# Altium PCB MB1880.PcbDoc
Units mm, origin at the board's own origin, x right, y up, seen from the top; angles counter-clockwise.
Board outline 30 x 30 mm, 2 copper layers (Top Layer, Bottom Layer), stack 1.499 mm thick; 19 components, 23 nets, 96 pads, 171 vias.
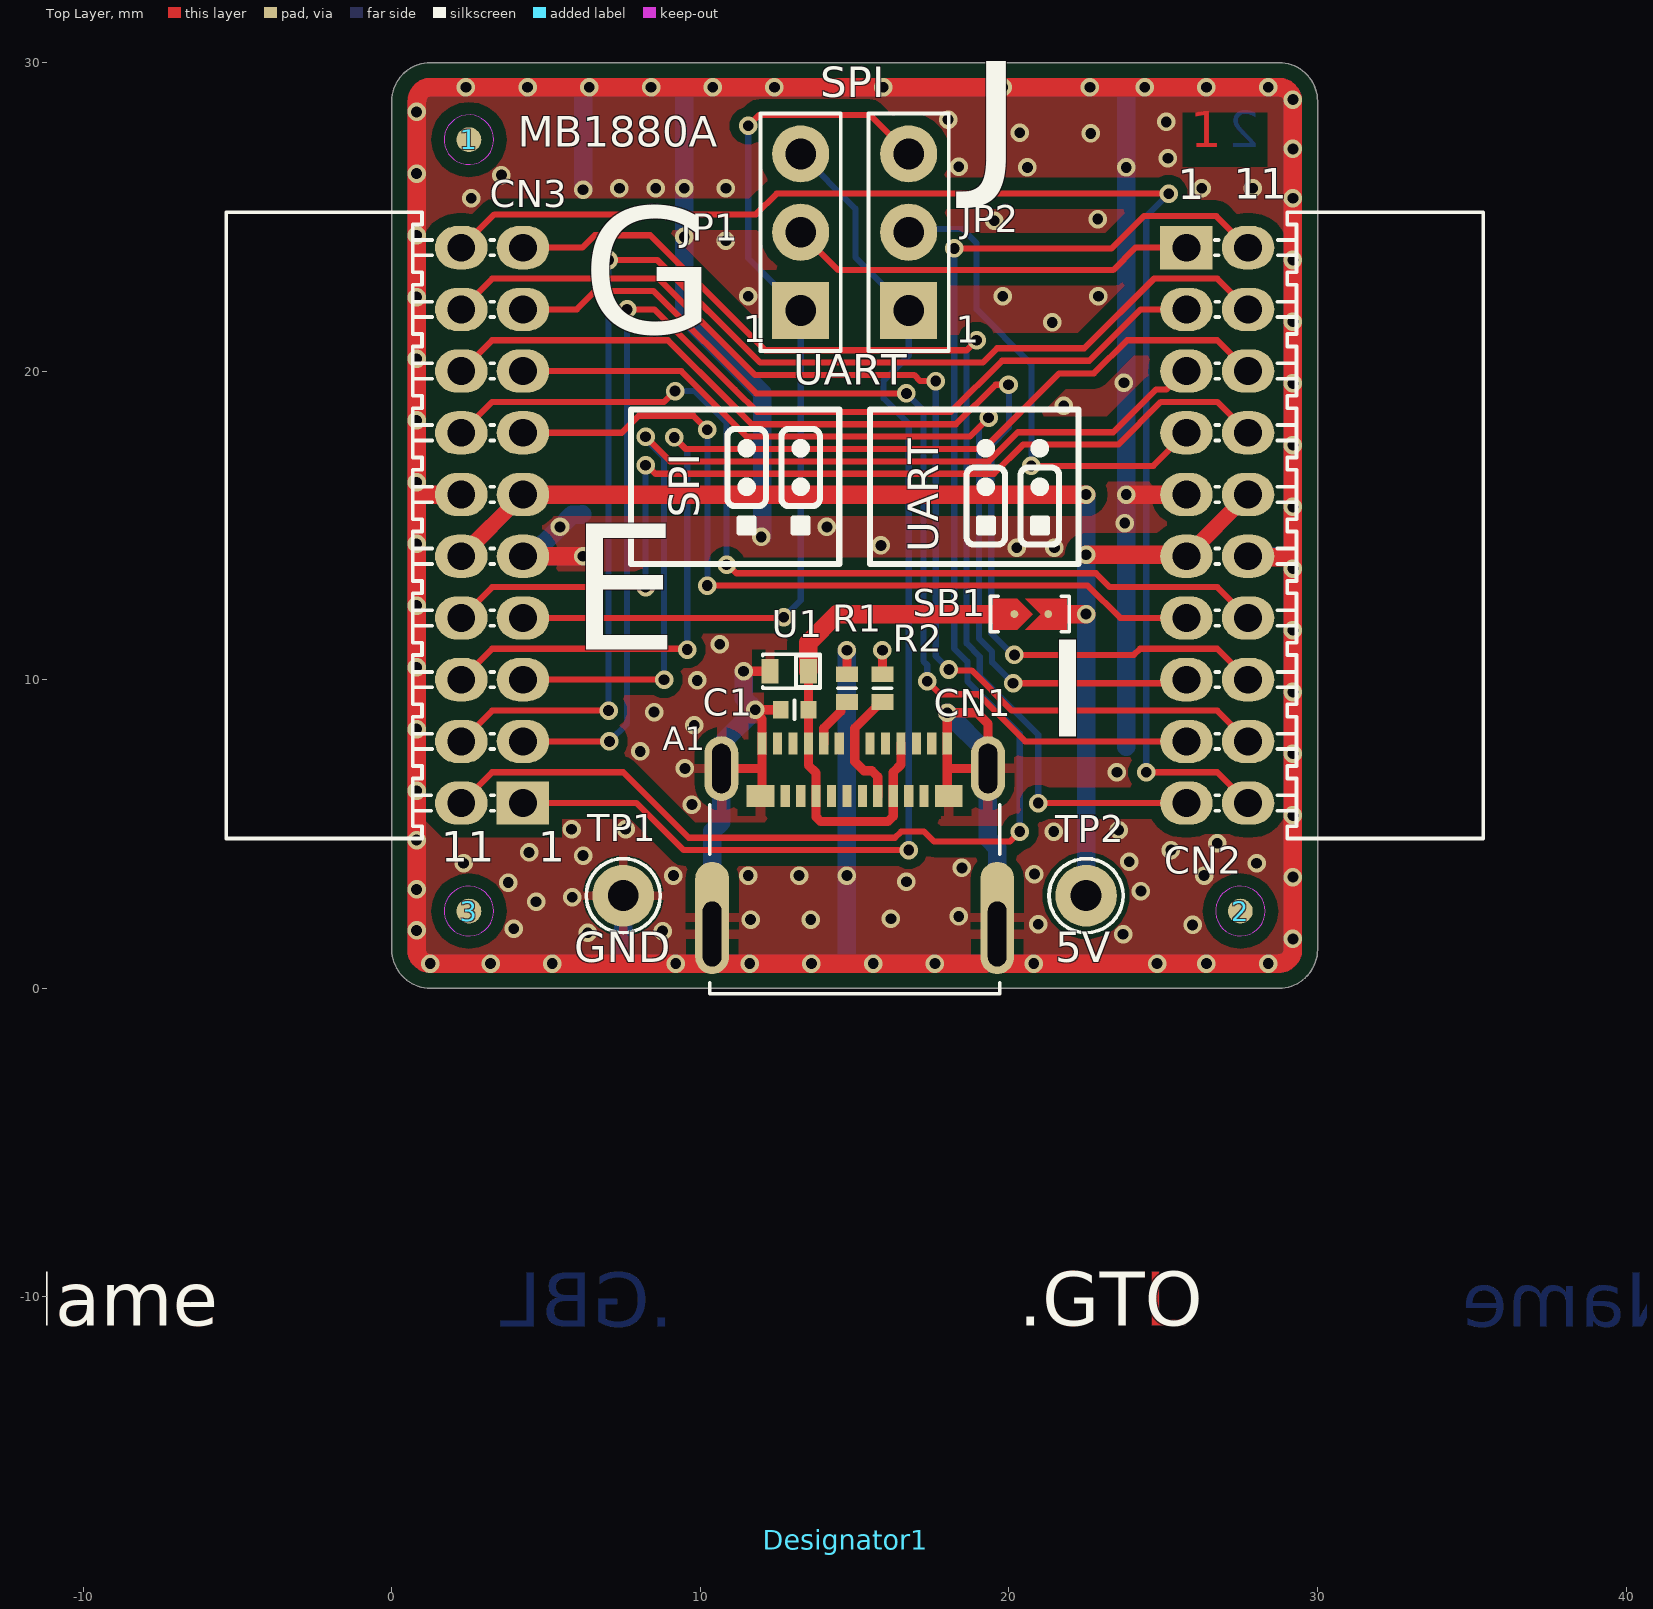
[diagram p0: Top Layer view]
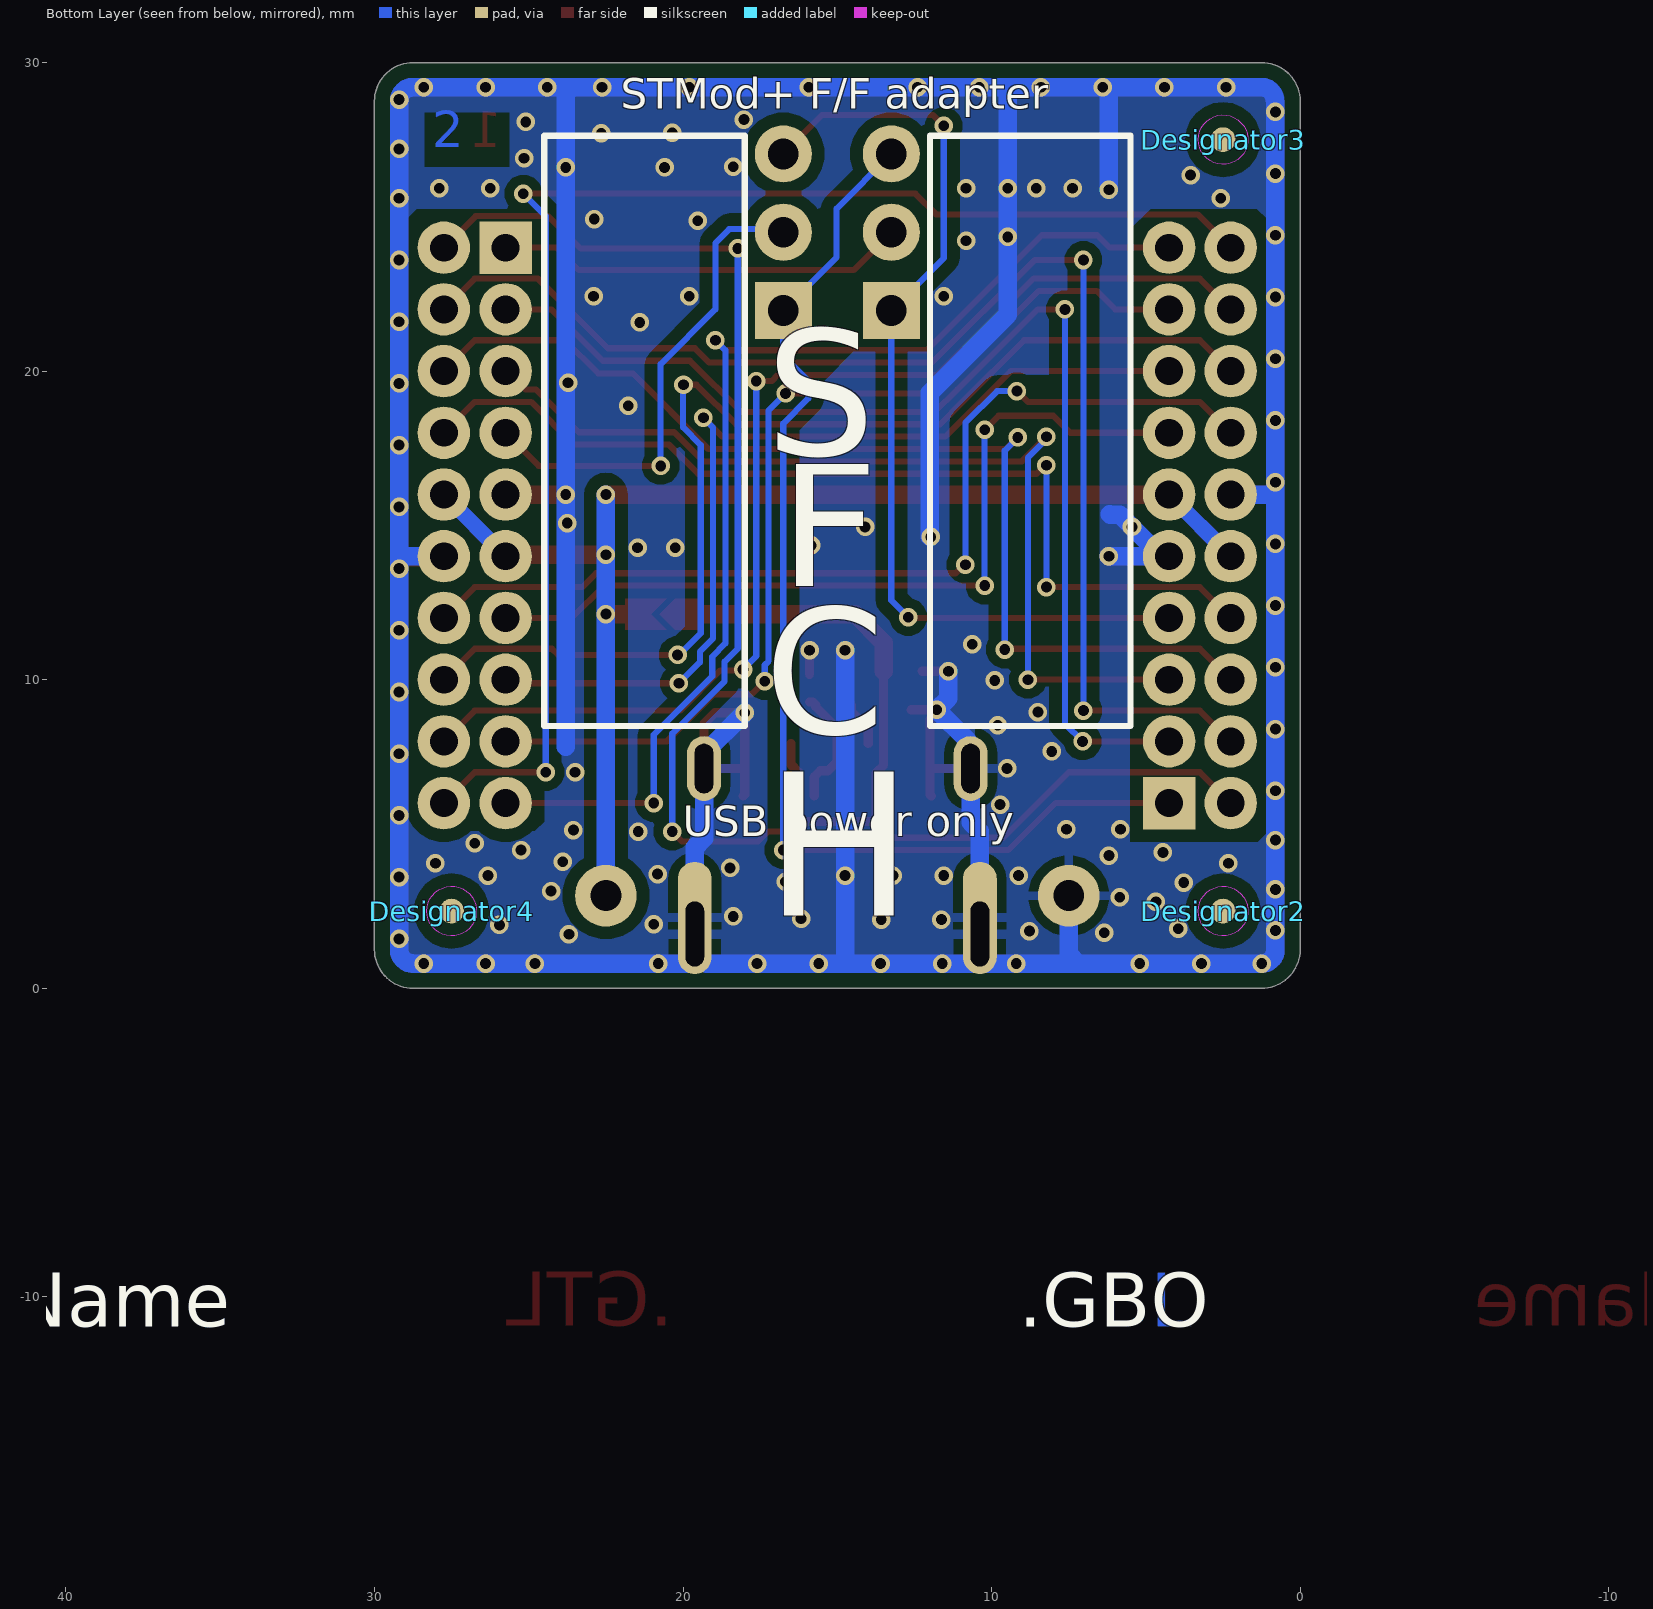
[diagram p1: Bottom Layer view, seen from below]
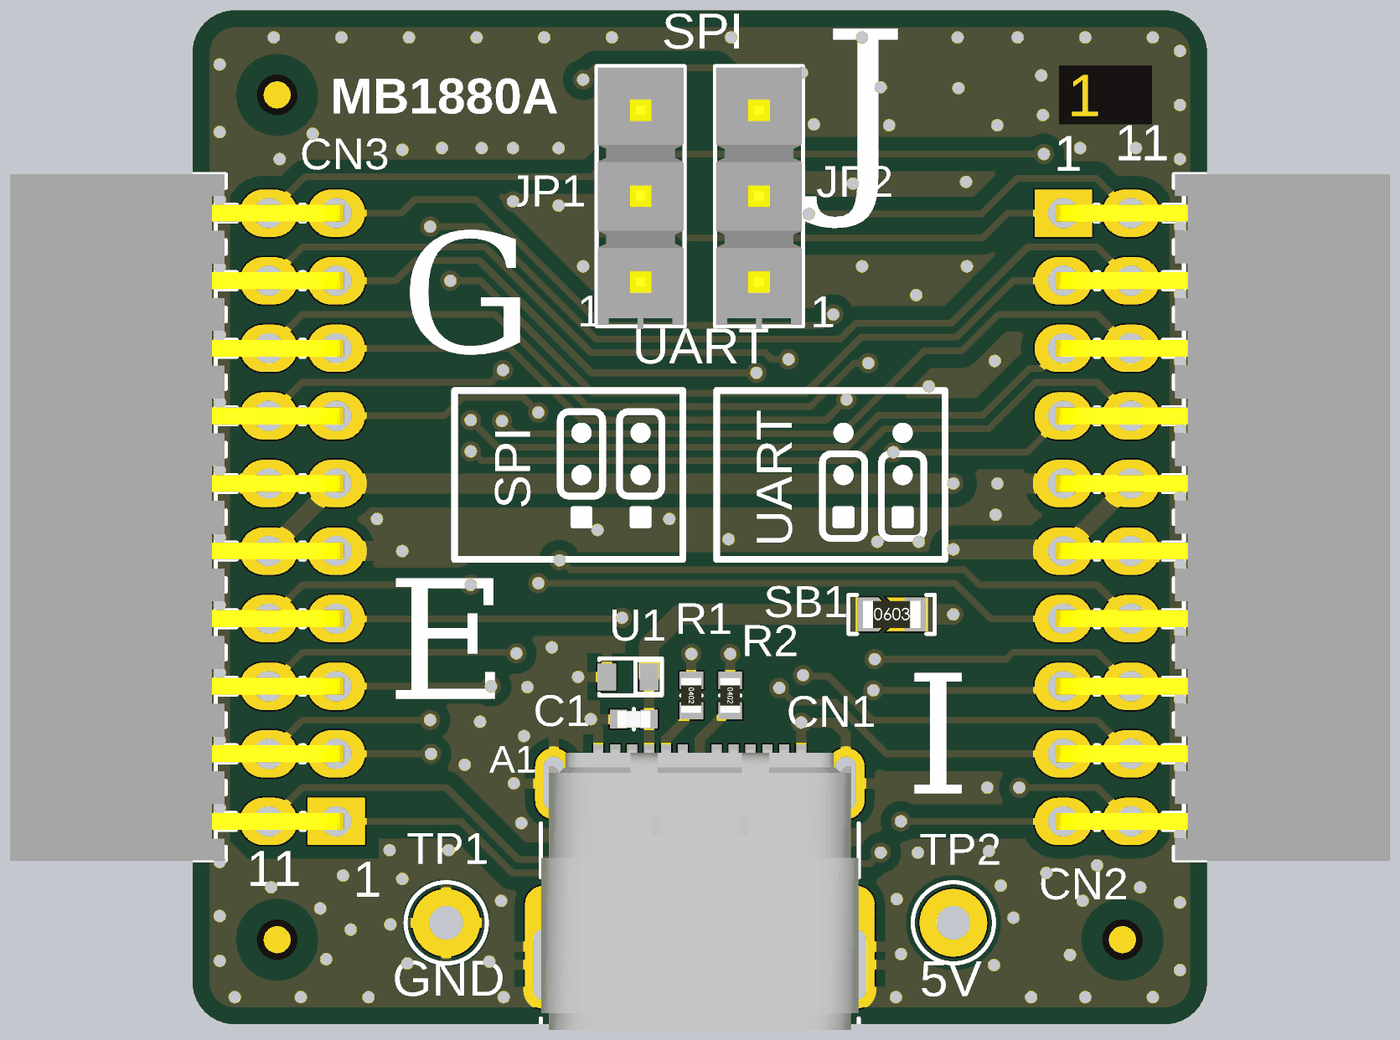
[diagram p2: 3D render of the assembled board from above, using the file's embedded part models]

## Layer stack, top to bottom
Top Solder: solder mask 0.02, Solder Resist, Dk 4.2
Top Layer: signal copper 0.0175
Dielectric 2: core 1.464, 8 x 7628, Dk 4.2
Bottom Layer: signal copper 0.0175
Bottom Solder: solder mask 0.02, Solder Resist, Dk 4.2

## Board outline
0,1.25 ccw(c1.25,1.25) 1.25,0 28.75,0 ccw(c28.75,1.25) 30,1.25 30,28.75 ccw(c28.75,28.75) 28.75,30 1.25,30 ccw(c1.25,28.75) 0,28.75

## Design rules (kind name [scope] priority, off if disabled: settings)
BoardOutlineClearance [All] p1: gap=0.5 ignorepadtopadclearanceinfootprint=FALSE
Clearance Clearance_Default [All] p1: gap=0.2 ignorepadtopadclearanceinfootprint=TRUE except(0.17: Region-Region; 0.225: SMDPad-Via; 0.3: Arc-Fill Arc-Region Track-Fill Track-Region SMDPad-Fill SMDPad-Region THPad-Via THPad-Fill THPad-Region Via-Fill Via-Poly Via-Region Fill-Fill Fill-Region Poly-Region; 0.4: Arc-Poly Track-Poly SMDPad-Poly THPad-Poly Fill-Poly Poly-Poly)
Clearance Clearance_Default_Same-Net [All] p2: gap=0.2 ignorepadtopadclearanceinfootprint=TRUE except(0.17: Region-Region; 0.225: SMDPad-Via; 0.3: Arc-Fill Arc-Region Track-Fill Track-Region SMDPad-Fill SMDPad-Region THPad-Via THPad-Fill THPad-Region Via-Fill Via-Region Fill-Fill Fill-Region; 0.4: Arc-Poly Track-Poly SMDPad-Poly THPad-Poly Via-Poly Fill-Poly Poly-Poly)
ComponentClearance [All] p1 off: gap=0.025 collisioncheckmode=3 verticalgap=2540 showdistances=TRUE
FanoutControl Fanout_BGA [IsBGA] p1: bgadir=Out bgaviamode=Closest fanoutstyle=Auto fanoutdirection=Alternating viagrid=0.025 // Fanout_BGA (Default Rule)
FanoutControl Fanout_LCC [IsLCC] p2: bgadir=Out bgaviamode=Closest fanoutstyle=Auto fanoutdirection=Alternating viagrid=0.025 // Fanout_LCC (Default Rule)
FanoutControl Fanout_SOIC [IsSOIC] p3: bgadir=Out bgaviamode=Closest fanoutstyle=Auto fanoutdirection=Alternating viagrid=0.025 // Fanout_SOIC (Default Rule)
FanoutControl Fanout_Small [(CompPinCount < 5)] p4: bgadir=Out bgaviamode=Closest fanoutstyle=Auto fanoutdirection=OutThenIn viagrid=0.025 // Fanout_Small (Default Rule)
FanoutControl Fanout_Default [All] p5: bgadir=Out bgaviamode=Closest fanoutstyle=Auto fanoutdirection=Alternating viagrid=0.025 // Fanout_Default (Default Rule)
Height [All] p1 off: minheight=0 maxheight=100 prefheight=0.5
HoleSize [All] p1: absolutevalues=TRUE maxlimit=10 minlimit=0.35 maxpercent=80.000 minpercent=20.000
HoleToHoleClearance [All] p1: gap=0.25 allowstackedmicrovias=TRUE
MinimumSolderMaskSliver [All] p1: minsoldermaskwidth=0.1
PlaneClearance [All] p1: clearance=0.6
PolygonConnect PolygonConnect__Default [All] p1: thpad.connectstyle=Relief thpad.reliefconductorwidth=0.3 thpad.reliefentries=4 thpad.polygonreliefangle="90 Angle" thpad.airgapwidth=0.3 smdpad.connectstyle=Relief smdpad.reliefconductorwidth=0.3 smdpad.reliefentries=4 smdpad.polygonreliefangle="90 Angle" smdpad.airgapwidth=0.3 via.connectstyle=Direct via.reliefconductorwidth=0.254 via.reliefentries=4 via.polygonreliefangle="45 Angle" via.airgapwidth=0.254
RoutingVias RoutingVias_Default [All] p1: holewidth=0.35 width=0.6 viastyle="Through Hole" minholewidth=0.35 minwidth=0.6 maxholewidth=0.35 maxwidth=0.6 useviatemplates=TRUE viatemplateguid#1={8C09205A-FF14-4BB6-B5C0-22CC2D486FF9} viatemplatename#1=v60h35m40
SilkToSilkClearance [All] p1: silktosilkclearance=0.2
SilkToSolderMaskClearance [IsPad] p1: minsilkscreentomaskgap=0 clearancetoexposedcopper=TRUE
SolderMaskExpansion [All] p1: expansion=0.05 istentingtop=FALSE
UnRoutedNet [All] p1: checkbadconnections=TRUE
Width Width_ALIMS [InNet('5V')] p1: maxlimit=10 minlimit=0.2 preferedwidth=0.5
Width Width_GND [InNet('GND')] p2: maxlimit=10 minlimit=0.2 preferedwidth=0.3
Width Width_Default [All] p3: maxlimit=10 minlimit=0.2 preferedwidth=0.2
16 further rules are at their usual default settings.

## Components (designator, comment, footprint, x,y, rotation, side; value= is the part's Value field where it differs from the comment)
1 "Comment" MIRE_PLACE_SMD_0P8MM 2.5,27.5 r0 top
2 "Comment" MIRE_PLACE_SMD_0P8MM 27.5,2.5 r0 top
3 "Comment" MIRE_PLACE_SMD_0P8MM 2.5,2.5 r0 top
C1 "" C0402 13.05,9.025 r0 top value=100pF
CN1 "USB_TYPE_C_Receptacle" CON_USB-TYPEC_MOLEX_2012670005 15,4.845 r0 top locked value=USB_C_2012670005
CN2 "Socket 10X2 STMod+" CON_SAMTEC_SQT-110-01-F-D-RA__STMOD+ 26.75,15 r90 top locked value="Socket 10X2"
CN3 "Socket 10X2 STMod+" CON_SAMTEC_SQT-110-01-F-D-RA__STMOD+ 3.25,15 r270 top locked value="Socket 10X2"
Designator1 "Comment" Sheetbox_2L2S -30.375,-23.225 r0 top
Designator2 "Comment" MIRE_PLACE_SMD_0P8MM 2.5,2.5 r180 bottom
Designator3 "Comment" MIRE_PLACE_SMD_0P8MM 2.5,27.5 r180 bottom
Designator4 "Comment" MIRE_PLACE_SMD_0P8MM 27.5,2.5 r180 bottom
JP1 "Jumper_Header 3x1 Fitted 1-2" CON_SAMTEC_TSW-103-07-F-S 13.25,24.5 r90 top locked value="Header 3x1"
JP2 "Jumper_Header 3x1 Fitted 1-2" CON_SAMTEC_TSW-103-07-F-S 16.75,24.5 r90 top locked value="Header 3x1"
R1 "Resistor" R0402 14.75,9.725 r270 top value=5K1
R2 "Resistor" R0402 15.9,9.725 r270 top value=5K1
SB1 "" SOLDER-BRIDGE_R0603-0R 20.675,12.125 r0 top
TP1 "Test_Point_PTH_1mm_2mm" TP_PTH_1MM_2MM 7.5,3 r0 top locked value=TP
TP2 "Test_Point_PTH_1mm_2mm" TP_PTH_1MM_2MM 22.5,3 r0 top locked value=TP
U1 "ESD-TRANSIL" ESD_QFN2_1P6X1_P125 12.875,10.275 r180 top value=ESDA7P60-1U1M

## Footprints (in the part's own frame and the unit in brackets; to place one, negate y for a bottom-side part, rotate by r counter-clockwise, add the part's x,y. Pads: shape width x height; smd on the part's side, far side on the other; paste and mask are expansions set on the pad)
C0402 [mm]
  rect 0.51x0.56 smd mask+0.05: 1(-0.45,0) 2(0.45,0)
  silkscreen extent 0,-0.3 0,0.3, body extent -0.5,-0.3 0.5,0.3, height 0.4
CON_SAMTEC_SQT-110-01-F-D-RA__STMOD+ [mm] "SQT-110-01-F-D-RA (connecteur SAMTEC pour interface STMod+ femelle coté Host) Pinning adapté non conforme SAMTEC."
  rect 1.4x1.7 / inner rect 1.7x1.7 / far side rect 1.7x1.7 hole 0.9 mask+0.05: 1(9,1)
  oval 1.4x1.7 / inner round 1.7 / far side round 1.7 hole 0.9 mask+0.05: 2(7,1) 3(5,1) 4(3,1) 5(1,1) 6(-1,1) 7(-3,1) 8(-5,1) 9(-7,1) 10(-9,1) 11(9,-1) 12(7,-1) 13(5,-1) 14(3,-1) 15(1,-1) 16(-1,-1) 17(-3,-1) 18(-5,-1) 19(-7,-1) 20(-9,-1)
  silkscreen extent -10.15,-8.62 10.15,0.07, body extent -10.15,-8.65 10.15,1.22, height 4
CON_SAMTEC_TSW-103-07-F-S [mm]
  rect 1.85x1.85 / inner round 1.85 / far side rect 1.85x1.85 hole 1 mask+0.05: 1(-2.54,0)
  round 1.85 hole 1 mask+0.05: 2(0,0) 3(2.54,0)
  silkscreen extent -3.85,-1.3 3.85,1.3, body extent -3.94,-1.37 3.91,1.37, height 8.38
CON_USB-TYPEC_MOLEX_2012670005 [mm] "MCD-02421"
  rect 0.3x0.7 smd mask+0.05: A1(-3,3.085) A2(-2.5,3.085) A3(-2,3.085) A4(-1.5,3.085) A5(-1,3.085) A6(-0.5,3.085) A7(0.5,3.085) A8(1,3.085) A9(1.5,3.085) A10(2,3.085) A11(2.5,3.085) A12(3,3.085) B2(2.25,1.385) B3(1.75,1.385) B4(1.25,1.385) B5(0.75,1.385) B6(0.25,1.385) B7(-0.25,1.385) B8(-0.75,1.385) B9(-1.25,1.385) B10(-1.75,1.385) B11(-2.25,1.385)
  rect 0.9x0.7 smd mask+0.05: B1(3.05,1.385) B12(-3.05,1.385)
  oval 1.1x2.1 hole 0.6 slot 1.6 at 90 deg mask+0.05: SH1(-4.32,2.275) SH2(4.32,2.275)
  oval 1.1x2.6 hole 0.6 slot 2.1 at 90 deg mask+0.05: SH3(-4.62,-3.085) SH4(4.62,-3.085)
  oval 1.1x3.6 all layers, no hole mask+0.05: SH3(-4.62,-2.55) SH4(4.62,-2.55)
  silkscreen extent -4.7,-5.02 4.7,1.1, body extent -4.69,-5.02 4.69,3.28, height 3.67
ESD_QFN2_1P6X1_P125 [mm]
  rect 0.55x0.8 smd mask+0.05: 1(-0.625,0) 2(0.625,0)
  silkscreen extent -1,-0.55 0.85,0.55, body extent -0.85,-0.55 0.85,0.55, height 0.61
MIRE_PLACE_SMD_0P8MM [mm]
  round 0.8 smd paste-10 mask+0.2: 1(0,0)
  Top Layer keep-out circle w0.01: c0,0 r0.804
R0402 [mm]
  rect 0.51x0.7 smd mask+0.05: 1(-0.45,0) 2(0.45,0)
  silkscreen extent 0,-0.3 0,0.3, body extent -0.52,-0.3 0.52,0.3, height 0.4
Sheetbox_2L2S [mil] "Sheetbox 2 layers / 2 silkscreens"
  round 20 on Mech16: 1(813.78,210.69) 1(2736.9,210.69)
SOLDER-BRIDGE_R0603-0R [mil]
  round 10 smd paste-393.7: 1(-19.68,0) 2(23.62,0)
  Top Layer region: -47.24,-19.69 -47.24,19.68 -15.75,19.68 3.94,0 -15.75,-19.69 -47.24,-19.69
  Top Layer region: -5.91,19.68 13.78,0 -5.91,-19.69 47.24,-19.69 47.24,19.68 -5.91,19.68
  silkscreen extent -50,-23 50,23, body extent -36,-20 36,20, height 22
TP_PTH_1MM_2MM [mm] "MCD-01506"
  round 2 hole 1 mask+0.05: 1(0,0)
  silkscreen extent -1.2,-1.2 1.2,1.2

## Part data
C1: library part MCD-00205, "Capacitor, MLCC, 100pF, 50V, NPO, 5%, 0402, T=0,5mm", Manufacturer=YAGEO, Manufacturer_Part_Number=CC0402JRNPO9BN101, Package=C0402
CN1: library part MCD-02421, "USB_TypeC, 24 pins, RA, SMD, T=3.71mm (USB Certified 3.1)", Manufacturer=MOLEX, Manufacturer_Part_Number=2012670005
CN2 CN3: library part MCD-00309, "Socket, 10x2, 2mm, RA, TH, T=6.35mm/2.29mm", Manufacturer=SAMTEC, Manufacturer_Part_Number=SQT-110-01-F-D-RA
JP1 JP2: library part MCD-00684, "Header, 3x1, 2.54mm, VR, TH, T=5.84mm/2.54mm", Manufacturer=SAMTEC, Manufacturer_Part_Number=TSW-103-07-F-S
R1 R2: library part MCD-00333, "Resistor, 5K1, 0402, +/-1%, 1/16W", Manufacturer=YAGEO, Manufacturer_Part_Number=RC0402FR-075K1L, Package=0402
SB1: library part MCD-00071, "Solder Bridge ON", Manufacturer=YAGEO, Manufacturer_Part_Number=RC0603JR-070RL, Package=SB0603
TP1 TP2: library part MCD-01506, "Test Point trought hole 1mm/2mm", Manufacturer=N/A
U1: library part MCD-00251, "High power transient voltage suppressor, 7V breakdown", Manufacturer=STMICROELECTRONICS, Manufacturer_HQ_COO=EU, Manufacturer_Part_Number=ESDA7P60-1U1M

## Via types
v1: diameter 0.6, hole 0.35, Top Layer to Bottom Layer, 171 vias

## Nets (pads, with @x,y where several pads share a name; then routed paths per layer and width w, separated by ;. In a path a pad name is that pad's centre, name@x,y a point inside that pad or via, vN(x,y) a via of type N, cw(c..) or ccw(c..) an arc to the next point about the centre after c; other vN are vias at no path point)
5V: CN2.6 CN2.15 CN3.6 CN3.15 SB1.2 TP2.1 | length 47.1
  Top Layer w0.4: SB1.2 21.8,12.125
  Top Layer w0.5: CN3.15 CN3.6 ; CN2.6@24.925,14.05 25.7,14.05 CN2.6 CN2.15
  Top Layer w0.6: CN3.6 v1(22.5,16) ; 21.8,12.125 v1(22.5,12.125) ; v1(22.5,14.05) CN2.6@24.925,14.05
  Bottom Layer w0.5: CN3.15 CN3.6 ; CN2.6 CN2.15
  Bottom Layer w0.6: TP2.1 v1(22.5,12.125) v1(22.5,14.05) v1(22.5,16)
GND: C1.1 CN1.A1 CN1.A12 CN1.B1 CN1.B12 CN1.SH1 CN1.SH2 CN1.SH3 CN1.SH4 CN2.5 CN2.16 CN3.5 CN3.16 R1.1 R2.1 TP1.1 U1.2 | length 328.8
  Top Layer w0.3: CN1.SH1 11.945,7.12 12,7.175 ; v1(11.4,10.275) U1.2 ; CN1.B12 12,6.28 12,7.175 ; C1.1 v1(11.775,9.025) 11.775,8.949 11.995,8.729 11.995,8.6 12,8.595 12,7.175 ; R1.1 v1(14.75,10.955) ; R2.1 v1(15.9,10.955) ; CN1.B1 18,6.28 18,7.105 ; 18,7.105 CN1.A12 v1(18,8.925) 18.964,8.925 19.32,8.569 CN1.SH2 18.015,7.12 18,7.105
  Top Layer w0.6: v1(0.8,16.4) 0.8,16 CN3.16 ; CN3.5 v1(6.2,14) ; CN1.SH3@10.38,1.76 CN1.SH3@10.38,0.93 ; CN1.SH1 CN1.SH1@10.72,7.08 ; CN1.SH4@19.62,2.295 19.62,1.76 CN1.SH4@19.62,1.18 ; v1(23.8,16) CN2.5 ; CN2.16@27.78,13.97 29.2,13.97 ; CN1.SH3@10.38,0.93 10.38,0.8 19.24,0.8 CN1.SH4@19.62,1.18 ; CN1.SH3@10.38,0.93 10.25,0.8 v1(1.245,0.8) cw(c1.245,1.2) 1.167,0.808 1.156,0.81 cw(c1.235,1.202) 1.083,0.832 1.072,0.837 cw(c1.226,1.206) 1.005,0.872 0.995,0.879 cw(c1.218,1.211) 0.936,0.927 0.927,0.936 cw(c1.211,1.218) 0.879,0.995 0.872,1.005 cw(c1.206,1.226) 0.837,1.072 0.832,1.083 cw(c1.202,1.235) 0.81,1.156 0.807,1.172 cw(c1.199,1.249) 0.8,1.225 0.8,28.6 cw(c1.766,28.6) 0.862,28.94 cw(c1.236,28.798) 1.159,29.191 1.165,29.192 cw(c1.245,28.8) 1.245,29.2 28.755,29.2 cw(c28.755,28.8) 28.833,29.192 28.843,29.19 cw(c28.765,28.798) 28.918,29.168 28.927,29.164 cw(c28.774,28.794) 28.996,29.127 29.004,29.121 cw(c28.782,28.789) 29.065,29.072 29.072,29.065 cw(c28.789,28.782) 29.121,29.004 29.127,28.996 cw(c28.794,28.774) 29.164,28.927 29.168,28.918 cw(c28.798,28.765) 29.19,28.843 29.199,28.8 29.2,28.794 29.2,1.245 cw(c28.8,1.245) 29.192,1.164 29.19,1.157 cw(c28.798,1.235) 29.168,1.082 29.164,1.073 cw(c28.794,1.226) 29.127,1.004 29.121,0.996 cw(c28.789,1.218) 29.072,0.936 29.037,0.9 28.995,0.873 cw(c28.774,1.206) 28.927,0.836 28.917,0.832 cw(c28.765,1.202) 28.844,0.81 28.836,0.808 cw(c28.755,1.2) 28.755,0.8 19.62,0.8 CN1.SH4@19.62,1.18
  Bottom Layer w0.6: CN3.16 0.925,16 v1@0.8,16.125 ; CN3.5 CN3.5@4.5,14 ; 6.166,15.366 6.15,15.35 5.85,15.35 v1(5.45,14.95) CN3.5@4.5,14 ; v1(6.2,14) CN3.5@4.5,14 ; v1(6.2,25.875) 6.2,29 v1(6.4,29.2) ; 7.2,0.8 7.5,1.1 TP1.1 ; CN1.SH3@10.38,1.76 CN1.SH3@10.38,0.93 ; CN1.SH3@10.38,2.295 10.38,5.08 10.68,5.38 CN1.SH1 10.776,7.216 10.776,8.026 v1(11.775,9.025) 11.4,9.4 v1(11.4,10.275) ; v1@12,14.625 12,19.3 9.475,21.825 v1(9.475,24.35) 9.475,29.2 ; v1(14.75,10.955) 14.75,0.85 14.8,0.8 ; v1(18,8.925) 19.32,7.605 CN1.SH2 19.32,4.855 19.62,4.555 19.62,2.295 19.62,1.76 CN1.SH4@19.62,1.18 ; 23.8,7.825 v1(23.8,16) v1(23.8,26.6) 23.8,29 23.6,29.2 ; CN2.16@27.78,13.97 CN2.16 29.2,14 ; v1@0.8,16.125 0.8,28.6 cw(c1.766,28.6) 0.862,28.94 cw(c1.236,28.798) 1.159,29.191 1.165,29.192 cw(c1.245,28.8) 1.245,29.2 9.475,29.2 ; v1@0.8,16.125 0.8,1.225 ccw(c1.199,1.249) 0.807,1.172 0.81,1.156 ccw(c1.202,1.235) 0.832,1.083 0.837,1.072 ccw(c1.206,1.226) 0.872,1.005 0.879,0.995 ccw(c1.211,1.218) 0.927,0.936 0.936,0.927 ccw(c1.218,1.211) 0.995,0.879 1.005,0.872 ccw(c1.226,1.206) 1.072,0.837 1.083,0.832 ccw(c1.235,1.202) 1.156,0.81 1.167,0.808 ccw(c1.245,1.2) v1(1.245,0.8) 10.25,0.8 CN1.SH3@10.38,0.93 ; 9.475,29.2 23.6,29.2 ; CN1.SH3@10.38,0.93 10.38,0.8 14.8,0.8 ; 14.8,0.8 19.24,0.8 CN1.SH4@19.62,1.18 ; CN1.SH4@19.62,1.18 19.62,0.8 28.755,0.8 ccw(c28.755,1.2) 28.836,0.808 28.844,0.81 ccw(c28.765,1.202) 28.917,0.832 28.927,0.836 ccw(c28.774,1.206) 28.995,0.873 29.037,0.9 29.072,0.936 ccw(c28.789,1.218) 29.121,0.996 29.127,1.004 ccw(c28.794,1.226) 29.164,1.073 29.168,1.082 ccw(c28.798,1.235) 29.19,1.157 29.192,1.164 ccw(c28.8,1.245) 29.2,1.245 v1(29.2,13.6) 29.2,13.97 29.2,28.794 29.199,28.8 29.19,28.843 ccw(c28.798,28.765) 29.168,28.918 29.164,28.927 ccw(c28.794,28.774) 29.127,28.996 29.121,29.004 ccw(c28.789,28.782) 29.072,29.065 29.065,29.072 ccw(c28.782,28.789) 29.004,29.121 28.996,29.127 ccw(c28.774,28.794) 28.927,29.164 28.918,29.168 ccw(c28.765,28.798) 28.843,29.19 28.833,29.192 ccw(c28.755,28.8) 28.755,29.2 23.6,29.2
  other v1: 3.2,0.8 5.2,0.8 9.2,0.8 11.6,0.8 13.6,0.8 15.6,0.8 17.6,0.8 20.8,0.8 24.8,0.8 26.4,0.8 28.4,0.8 29.2,1.6 23.7,1.75 6.35,1.8 8.775,1.85 0.8,1.875 3.95,1.925 25.95,2.05 20.95,2.075 11.625,2.225 13.575,2.225 16.175,2.25 18.375,2.325 4.675,2.8 5.85,2.95 24.275,3.15 0.8,3.2 3.775,3.425 16.675,3.45 29.2,3.6 9.125,3.65 11.55,3.65 13.2,3.65 14.75,3.65 26.325,3.65 20.825,3.7 18.475,3.9 2.325,4.05 28.025,4.05 23.9,4.1 6.2,4.3 4.45,4.4 25.25,4.475 26.75,4.7 0.8,4.8 21.45,5.075 23.55,5.125 5.825,5.15 7.575,5.15 29.2,5.6 9.725,5.95 0.8,6.4 23.5,7 9.5,7.125 29.2,7.6 8.05,7.675 0.8,8.4 9.8,8.525 8.5,8.95 29.2,9.6 9.9,9.975 0.8,10.4 10.625,11.15 29.2,11.6 0.8,12.4 20.25,14.275 21.475,14.275 15.85,14.35 0.8,14.4 11.975,14.625 14.1,14.95 23.75,15.075 29.2,15.6 29.2,17.6 0.8,18.4 21.775,18.875 29.2,19.6 23.725,19.625 0.8,20.4 21.4,21.575 29.2,21.6 0.8,22.4 11.55,22.425 19.8,22.425 22.9,22.425 29.2,23.6 10.825,24.225 0.8,24.4 19.525,24.875 22.875,24.925 2.575,25.6 29.2,25.6 7.375,25.925 8.55,25.925 9.475,25.925 10.825,25.925 26.25,25.925 27.9,25.925 3.55,26.35 0.8,26.4 20.6,26.6 18.375,26.625 25.15,26.9 29.2,27.2 22.65,27.7 20.35,27.725 25.1,28.075 18.025,28.15 0.8,28.4 29.2,28.8 2.4,29.2 4.4,29.2 8.4,29.2 10.4,29.2 12.4,29.2 15.925,29.2 19.8,29.2 22.625,29.2 24.4,29.2 26.4,29.2 28.4,29.2
NetC1_2: C1.2 CN1.A4 CN1.A9 CN1.B4 CN1.B9 SB1.1 U1.1 | length 17.9
  Top Layer w0.3: U1.1 C1.2 CN1.A4 13.5,7.225 13.75,6.975 CN1.B9 13.75,5.55 13.9,5.4 16.075,5.4 16.25,5.575 CN1.B4 16.25,7 16.5,7.25 CN1.A9
  Top Layer w0.4: 19.475,12.125 SB1.1
  Top Layer w0.6: U1.1 13.5,11.2 14.425,12.125 19.475,12.125
NetCN1_A5: CN1.A5 R1.2 | length 1.7
  Top Layer w0.3: CN1.A5 14,8.218 14,8.425 14.55,8.975 14.55,9.17 14.655,9.275 R1.2
NetCN1_B5: CN1.B5 R2.2 | length 3.9
  Top Layer w0.3: CN1.B5 15.75,6.85 15.55,7.05 15.3,7.05 15,7.35 15,8.425 15.7,9.125 15.7,9.17 15.805,9.275 R2.2
NetCN2_1: CN2.1 JP1.2 | length 13.3
  Top Layer w0.2: JP1.2 14.475,23.275 23.375,23.275 24.1,24 CN2.1
NetCN2_2: CN2.2 CN3.2 | length 37.9
  Top Layer w0.2: CN3.2 v1(7.05,8) ; v1(7.625,22) 8.512,22 10.819,19.694 11.114,19.398 11.837,18.675 18.116,18.675 19.778,20.338 22.603,20.338 24.266,22 CN2.2
  Bottom Layer w0.2: v1(7.05,8) 7.625,8.575 v1(7.625,22)
NetCN2_3: CN2.3 CN3.3 | length 31.8
  Top Layer w0.2: CN3.3 v1(8.825,10) ; v1(8.225,17.875) 9.025,17.075 19.344,17.075 20.289,18.02 23.379,18.02 24.76,19.401 25.101,19.401 25.7,20 CN2.3
  Bottom Layer w0.2: v1(8.225,17.875) 8.225,17.799 8.825,17.199 v1(8.825,10)
NetCN2_4: CN2.4 JP2.2 | length 15.9
  Top Layer w0.2: v1(20.725,16.925) 24.675,16.925 CN2.4
  Bottom Layer w0.2: JP2.2 16.85,24.6 18.5,24.6 18.95,24.15 18.95,22 20.725,20.225 v1(20.725,16.925)
NetCN2_7: CN2.7 CN3.7 | length 27.4
  Top Layer w0.2: CN3.7 7.45,18 8,18.55 9.775,18.55 v1(10.225,18.1) ; v1(10.225,13.05) 22.55,13.05 23.6,12 CN2.7
  Bottom Layer w0.2: v1(10.225,13.05) v1(10.225,18.1)
NetCN2_8: CN2.8 CN3.8 | length 31.1
  Top Layer w0.2: CN3.8 9.381,20 11.506,17.875 18.73,17.875 v1(19.34,18.485) ; v1(20.132,9.882) 25.632,9.882 CN2.8
  Bottom Layer w0.2: v1(19.34,18.485) 19.34,18.483 19.025,18.168 19.025,11.339 19.454,10.909 19.454,10.56 v1(20.132,9.882)
NetCN2_9: CN2.9 CN3.9 | length 32.9
  Top Layer w0.2: CN3.9 6,22 6.6,22.6 8.478,22.6 11.803,19.275 v1(16.675,19.275) ; v1(17.35,9.95) 17.775,9.525 19,9.525 20.525,8 CN2.9
  Bottom Layer w0.2: v1(16.675,19.275) 17.225,18.725 17.225,10.6 17.35,10.475 v1(17.35,9.95)
NetCN2_10: CN2.10 CN3.10 | length 37.4
  Top Layer w0.2: CN3.10 6.175,24 6.575,24.4 8.375,24.4 12.1,20.675 18.625,20.675 v1(18.95,21) ; v1(20.95,6) CN2.10
  Bottom Layer w0.2: v1(18.95,21) 18.625,20.675 18.625,11.173 19.054,10.743 19.054,10.111 20.95,8.216 v1(20.95,6)
NetCN2_11: CN2.11 CN3.11 | length 49.9
  Top Layer w0.2: CN3.11 3.25,7 7.5,7 9.625,4.875 16.301,4.875 16.501,5.075 17.25,5.075 17.575,4.75 20.025,4.75 v1(20.35,5.075) ; v1(18.225,23.975) 23.325,23.975 24.375,25.025 26.725,25.025 CN2.11
  Bottom Layer w0.2: v1(18.225,23.975) 18.225,11.007 18.654,10.578 18.654,9.946 20.35,8.25 v1(20.35,5.075)
NetCN2_12: CN2.12 CN3.12 | length 43.4
  Top Layer w0.2: CN3.12 3.25,9 v1(7.025,9) ; v1(7.025,23.6) 8.609,23.6 11.934,20.275 19.15,20.275 19.613,20.738 22.438,20.738 24.7,23 26.75,23 CN2.12
  Bottom Layer w0.2: v1(7.025,9) v1(7.025,23.6)
NetCN2_13: CN2.13 CN3.13 | length 35.4
  Top Layer w0.2: CN3.13 3.25,11 9.55,11 v1(9.575,10.975) ; v1(9.15,17.85) 9.525,17.475 19.178,17.475 21.627,19.923 22.755,19.923 23.831,21 26.75,21 CN2.13
  Bottom Layer w0.2: v1(9.15,17.85) 9.575,17.425 v1(9.575,10.975)
NetCN2_14: CN2.14 CN3.14 | length 31.4
  Top Layer w0.2: CN3.14 3.25,13 5.95,13 v1(8.225,13) ; v1(8.225,16.95) 8.267,16.95 8.542,16.675 19.51,16.675 20.455,17.62 23.545,17.62 24.925,19 26.75,19 CN2.14
  Bottom Layer w0.2: v1(8.225,13) v1(8.225,16.95)
NetCN2_17: CN2.17 CN3.17 | length 31.8
  Top Layer w0.2: CN3.17 3.25,19 8.825,19 v1(9.179,19.354) ; v1(10.85,13.725) 10.892,13.725 11.167,13.45 22.816,13.45 23.266,13 26.75,13 CN2.17
  Bottom Layer w0.2: v1(9.179,19.354) 9.82,19.354 10.85,18.324 v1(10.85,13.725)
NetCN2_18: CN2.18 CN3.18 | length 37.2
  Top Layer w0.2: CN3.18 3.25,21 8.947,21 10.948,18.998 11.672,18.275 18.281,18.275 19.566,19.56 v1(19.985,19.56) ; v1(20.175,10.8) 24.05,10.8 24.25,11 26.75,11 CN2.18
  Bottom Layer w0.2: v1(19.985,19.56) 20,19.545 20,18.865 20,18.175 19.425,17.6 19.425,11.504 20.129,10.8 v1(20.175,10.8)
NetCN2_19: CN2.19 CN3.19 | length 37.4
  Top Layer w0.2: CN3.19 3.25,23 8.644,23 11.769,19.875 16.925,19.875 17.125,19.675 v1(17.625,19.675) ; v1(18.054,10.329) 18.084,10.3 18.791,10.3 20.091,9 26.75,9 CN2.19
  Bottom Layer w0.2: v1(17.625,19.675) 17.625,10.766 18.054,10.336 v1(18.054,10.329)
NetCN2_20: CN2.20 CN3.20 | length 46.4
  Top Layer w0.2: CN3.20 3.325,25.075 11.8,25.075 12.475,25.75 v1(25.175,25.75) ; v1(24.45,7) 26.75,7 CN2.20
  Bottom Layer w0.2: v1(24.45,7) 24.45,25.025 v1(25.175,25.75)
NetCN3_1: CN3.1 JP1.3 JP2.1 | length 37.8
  Top Layer w0.2: CN3.1 7.934,6 9.459,4.475 v1(16.75,4.475)
  Bottom Layer w0.2: JP1.3 15.025,25.265 15.025,23.685 JP2.1 16.75,20.5 15.937,19.687 15.937,19.112 16.75,18.3 v1(16.75,4.475)
NetCN3_4: CN3.4 JP1.1 JP2.3 | length 31.2
  Top Layer w0.2: CN3.4 12.675,12 v1(12.7,12.025) ; v1(11.55,27.95) 11.9,28.3 15.49,28.3 JP2.3
  Bottom Layer w0.2: v1(11.55,27.95) 11.55,23.66 JP1.1 13.25,12.575 v1(12.7,12.025)
pads on no net: 1.1 2.1 3.1 CN1.A2 CN1.A3 CN1.A6 CN1.A7 CN1.A8 CN1.A10 CN1.A11 CN1.B2 CN1.B3 CN1.B6 CN1.B7 CN1.B8 CN1.B10 CN1.B11 Designator1.1 Designator2.1 Designator3.1 Designator4.1

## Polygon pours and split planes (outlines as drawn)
GND on Top Layer "GND_L01_P000" (solid, remove dead copper, pour order 0): -0.25,30.25 -0.25,-0.25 30.25,-0.25 30.25,30.25
GND on Bottom Layer "GND_L02_P001" (solid, remove dead copper, pour order 1): -0.25,30.25 -0.25,-0.25 30.25,-0.25 30.25,30.25

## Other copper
Top Layer:
  pour cut-out: 16.1,11.425 16.45,11.075 16.45,10.26 16.76,9.95 19.625,9.95 19.75,10.075 19.75,11.225 19.55,11.425
  pour cut-out: 8.133,13.7 10.15,13.7 10.15,12.5 9.9,12.25 8.35,12.25 8.133,12.467 8.133,12.675
  pour cut-out: 28.9,24.275 28.9,5.675 28.225,5 26.125,5 26.125,24.275
  pour cut-out: 1.1,24.275 1.1,5.431 1.631,4.9 3.4,4.9 3.4,24.15 3.275,24.275
  text "1" at 25.878,26.873 h2
Bottom Layer:
  pour cut-out: 24.8,5.1 28.45,5.1 28.9,5.55 28.9,24.975 28.625,25.25 24.5,25.25 24.5,5.4
  pour cut-out: 9.82,19.863 9.819,19.862 8.062,19.862 7.875,19.675 7.875,18.325 8.2,18 9.7,18 10.1,18.4 10.1,19.583
  pour cut-out: 13.76,20.635 14.48,20.635 15.428,19.687 15.937,19.687 16.35,20.1 16.35,22.8 15.65,23.5 14.175,23.5 13.76,23.085
  pour cut-out: 2.085,25.25 1.4,25.25 1.1,24.95 1.1,5.025 1.375,4.75 5.5,4.75 5.5,24.6 4.85,25.25
  text "2" at 28.128,26.873 h2
Multi-Layer:
  pour cut-out: 25.628,28.373 25.628,26.623 28.378,26.623 28.378,28.373

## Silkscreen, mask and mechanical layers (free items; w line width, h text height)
Top Overlay:
  circle w0.35: c21,15 r0.1
  circle w0.35: c21,17.5 r0.125
  circle w0.35: c21,16.25 r0.125
  circle w0.35: c19.25,16.25 r0.125
  circle w0.35: c19.25,17.5 r0.125
  circle w0.35: c19.25,15 r0.1
  circle w0.35: c11.5,15 r0.1
  circle w0.35: c11.5,17.5 r0.125
  circle w0.35: c11.5,16.25 r0.125
  circle w0.35: c13.25,16.25 r0.125
  circle w0.35: c13.25,17.5 r0.125
  circle w0.35: c13.25,15 r0.1
  lines w0.15: 11.25,14.75 11.75,14.75 11.75,15.25 11.25,15.25 11.25,14.75 ; 13,14.75 13,15.25 13.5,15.25 13.5,14.75 13,14.75 ; 19,14.75 19,15.25 19.5,15.25 19.5,14.75 19,14.75 ; 20.75,14.75 20.75,15.25 21.25,15.25 21.25,14.75 20.75,14.75
  lines w0.2: 7.75,13.75 7.75,18.75 14.5,18.75 14.5,13.75 7.75,13.75 ; 10.875,15.875 ccw(c11.125,15.875) 11.125,15.625 11.875,15.625 ccw(c11.875,15.875) 12.125,15.875 12.125,17.875 ccw(c11.875,17.875) 11.875,18.125 11.5,18.125 11.125,18.125 ccw(c11.125,17.875) 10.875,17.875 10.875,17.25 10.875,15.875 ; 12.625,15.875 ccw(c12.875,15.875) 12.875,15.625 13.625,15.625 ccw(c13.625,15.875) 13.875,15.875 13.875,17.875 ccw(c13.625,17.875) 13.625,18.125 13.25,18.125 12.875,18.125 ccw(c12.875,17.875) 12.625,17.875 12.625,17.25 12.625,15.875 ; 15.5,13.75 22.25,13.75 22.25,18.75 15.5,18.75 15.5,13.75 ; 18.625,14.625 ccw(c18.875,14.625) 18.875,14.375 19.625,14.375 ccw(c19.625,14.625) 19.875,14.625 19.875,16.625 ccw(c19.625,16.625) 19.625,16.875 19.25,16.875 18.875,16.875 ccw(c18.875,16.625) 18.625,16.625 18.625,16 18.625,14.625 ; 20.375,14.625 ccw(c20.625,14.625) 20.625,14.375 21.375,14.375 ccw(c21.375,14.625) 21.625,14.625 21.625,16.625 ccw(c21.375,16.625) 21.375,16.875 21,16.875 20.625,16.875 ccw(c20.625,16.625) 20.375,16.625 20.375,16 20.375,14.625
  text "SPI" at 13.877,28.556 h1.7
  text "MB1880A" at 4.075,26.95 h1.7
  text "11" at 27.277,25.254 h1.7
  text "J" at 18.625,24.875 h9
  text "G" at 6.15,19.875 h7
  text "UART" at 13.006,19.24 h1.7
  text "SPI" at 10.294,15.252 h1.7 r90
  text "UART" at 18.035,14.131 h1.7 r90
  text "E" at 5.75,9.625 h7
  text "I" at 21.075,6.825 h7
  text "11" at 1.602,3.779 h1.7
  text "GND" at 5.908,0.526 h1.7
  text "5V" at 21.508,0.515 h1.7
Bottom Overlay:
  lines w0.2: 5.5,8.5 5.5,27.625 12,27.625 12,8.5 5.5,8.5 ; 18,8.5 24.5,8.5 24.5,27.625 18,27.625 18,8.5
  text "STMod+ F/F adapter" at 22.014,28.173 h1.7
  text "S" at 17.325,15.925 h7
  text "F" at 16.875,11.7 h7
  text "C" at 17.375,6.9 h7
  text "USB power only" at 20.01,4.606 h1.7
  text "H" at 17.35,0.825 h8
Top Solder:
  rectangle: 25.628,26.623 28.378,28.373
Bottom Solder:
  rectangle: 25.628,26.623 28.378,28.373
M1-Board Shape:
  the board outline again, w0.1
Drill Drawing:
  drawing of 192 lines, arcs and shapes, not listed
  text "PCB SPECIFICATIONS :" at -47.014,69.229 h3
  text "A.   MATERIAL :" at -47.014,65.229 h3
  text "FR-4" at -8.514,65.229 h3
  text "TG-170" at 7.986,65.229 h3
  text "TG-150" at 26.236,65.229 h3
  text "X  TG-140" at 42.236,65.229 h3
  text "B.   MATERIAL FAMILY :" at -47.014,62.229 h3
  text "N/A" at -8.514,62.229 h3
  text "C.   SOLDERMASK COLOR :" at -47.014,59.229 h3
  text "GREEN" at -8.514,59.229 h3
  text "WHITE" at 7.986,59.229 h3
  text "RED" at 26.236,59.229 h3
  text "X  Blue ink PANTONE 2955" at 42.236,59.229 h3
  text "D.   SILKSCREEN COLOR :" at -47.014,56.229 h3
  text "X  WHITE" at -8.514,56.229 h3
  text "YELLOW" at 7.986,56.229 h3
  text "BLACK" at 26.236,56.229 h3
  text "Blue ink PANTONE 2955" at 42.236,56.229 h3
  text "E.   SURFACE FINISH :" at -47.014,53.229 h3
  text "X  ENIG" at -8.514,53.229 h3
  text "IMMERSION SILVER" at 7.986,53.229 h3
  text "IMMERSION TIN" at 42.236,53.229 h3
  text "HASL" at -8.514,50.229 h3
  text "HASL (PB-FREE)" at 7.986,50.229 h3
  text "GOLDEN FINGER" at 42.236,50.229 h3
  text "F.   IMPEDANCE CONTROL :" at -47.014,47.229 h3
  text "X  NO" at -8.514,47.229 h3
  text "YES  (SEE IMPEDANCE TABLE FOR DETAIL INFORMATION)" at 7.986,47.229 h3
  text "G.   THROUGH VIA :" at -47.014,44.229 h3
  text "PLUG THE VIAS WHICH ARE COVERED WITH SOLDERMASK ONE OR TWO SIDE." at -8.514,44.229 h3
  text "PLUG MATERIAL :" at -8.514,41.229 h3
  text "X  SOLDERMASK" at 16.986,41.229 h3
  text "NON-CONDUCTIVE EPOXY." at 42.236,41.229 h3
  text "H.   STACK-UP :" at -47.014,38.229 h3
  text "SEE LAYER STACK-UP SEQUENCE FOR OVERALL THICKNESS." at -8.514,38.229 h3
  text "MINIMUM PARAMETERS" at -46.225,31.625 h3
  text "Layer" at 40.559,29.475 h2
  text "Name" at 48.933,29.475 h2
  text "Material" at 65.13,29.475 h2
  text "Thickness" at 79.684,29.475 h2
  text "Constant" at 91.639,29.475 h2
  text "DEFAULT" at -50.357,25.873 h3
  text "Top Overlay" at 48.933,25.475 h2
  text "Top Solder" at 48.933,21.475 h2
  text "Solder Resist" at 65.13,21.475 h2
  text "0.020mm" at 79.684,21.475 h2
  text "4.2" at 91.639,21.475 h2
  text "TRACKS : 0.20mm           / GAPS : 0.20mm" at -50.357,20.123 h3
  text "1" at 40.559,17.475 h2
  text "Top Layer" at 48.933,17.475 h2
  text "Copper" at 65.13,17.475 h2
  text "0.018mm" at 79.684,17.475 h2
  text "Dielectric 2" at 48.933,13.475 h2
  text "8 x 7628" at 65.13,13.475 h2
  text "1.464mm" at 79.684,13.475 h2
  text "4.2" at 91.639,13.475 h2
  text "PCB : TYPE 2" at -41.152,12.322 h3
  text "2" at 40.558,9.475 h2
  text "Bottom Layer" at 48.933,9.475 h2
  text "Copper" at 65.13,9.475 h2
  text "0.018mm" at 79.684,9.475 h2
  text "ASPECT-RATIO, AXE Z :" at -41.152,6.822 h3
  text "Bottom Solder" at 48.933,5.475 h2
  text "Solder Resist" at 65.13,5.475 h2
  text "0.020mm" at 79.684,5.475 h2
  text "4.2" at 91.639,5.475 h2
  text "Bottom Overlay" at 48.933,1.475 h2
  text "< 6:1 / LEVEL \"A\"" at -41.134,0.074 h3
  text "Symbol" at -44.726,-29.542 h3
  text "Count" at -32.975,-29.542 h3
  text "Hole Size" at -20.756,-29.542 h3
  text "Plated" at 2.084,-29.542 h3
  text "Hole Type" at 12.4,-29.542 h3
  text "Drill Layer Pair" at 27.419,-29.542 h3
  text "Via/Pad" at 55.886,-29.542 h3
  text "Pad Shape" at 68.193,-29.542 h3
  text "2" at -32.975,-34.72 h2.5
  text "0.600mm (23.62mil)" at -20.756,-34.72 h2.5
  text "PTH" at 2.084,-34.72 h2.5
  text "Slot" at 12.4,-34.72 h2.5
  text "Top Layer - Bottom Layer" at 27.419,-34.72 h2.5
  text "Pad" at 55.886,-34.72 h2.5
  text "Rounded" at 68.193,-34.72 h2.5
  text "2" at -32.975,-39.897 h2.5
  text "0.600mm (23.62mil)" at -20.756,-39.897 h2.5
  text "PTH" at 2.084,-39.897 h2.5
  text "Slot" at 12.4,-39.897 h2.5
  text "Top Layer - Bottom Layer" at 27.419,-39.897 h2.5
  text "Pad" at 55.886,-39.897 h2.5
  text "Rounded" at 68.193,-39.897 h2.5
  text "8" at -32.975,-45.075 h2.5
  text "1.000mm (39.37mil)" at -20.756,-45.075 h2.5
  text "PTH" at 2.084,-45.075 h2.5
  text "Round" at 12.4,-45.075 h2.5
  text "Top Layer - Bottom Layer" at 27.419,-45.075 h2.5
  text "Pad" at 55.886,-45.075 h2.5
  text "Rounded" at 68.193,-45.075 h2.5
  text "40" at -32.975,-50.252 h2.5
  text "0.900mm (35.43mil)" at -20.756,-50.252 h2.5
  text "PTH" at 2.084,-50.252 h2.5
  text "Round" at 12.4,-50.252 h2.5
  text "Top Layer - Bottom Layer" at 27.419,-50.252 h2.5
  text "Pad" at 55.886,-50.252 h2.5
  text "(Mixed)" at 68.193,-50.252 h2.5
  text "171" at -32.975,-55.429 h2.5
  text "0.350mm (13.78mil)" at -20.756,-55.429 h2.5
  text "PTH" at 2.084,-55.429 h2.5
  text "Round" at 12.4,-55.429 h2.5
  text "Top Layer - Bottom Layer" at 27.419,-55.429 h2.5
  text "Via" at 55.886,-55.429 h2.5
  text "Rounded" at 68.193,-55.429 h2.5
  text "223 Total" at -32.975,-60.607 h2.5
  text "Slot definitions :" at -44.726,-64.231 h2.5
  text "Routed Path Length" at -27.665,-64.231 h2.5
  text "= Calculated from tool start centre position to tool end centre position." at -6.529,-64.231 h2.5
  text "Hole Length" at -27.665,-66.302 h2.5
  text "= Routed Path Length + Tool Size = Slot length as defined in the PCB layout" at -14.376,-66.302 h2.5

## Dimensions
28.75,30 to 28.75,0 on M2-Board Dimensions
0,28.75 to 30,28.75 on M2-Board Dimensions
